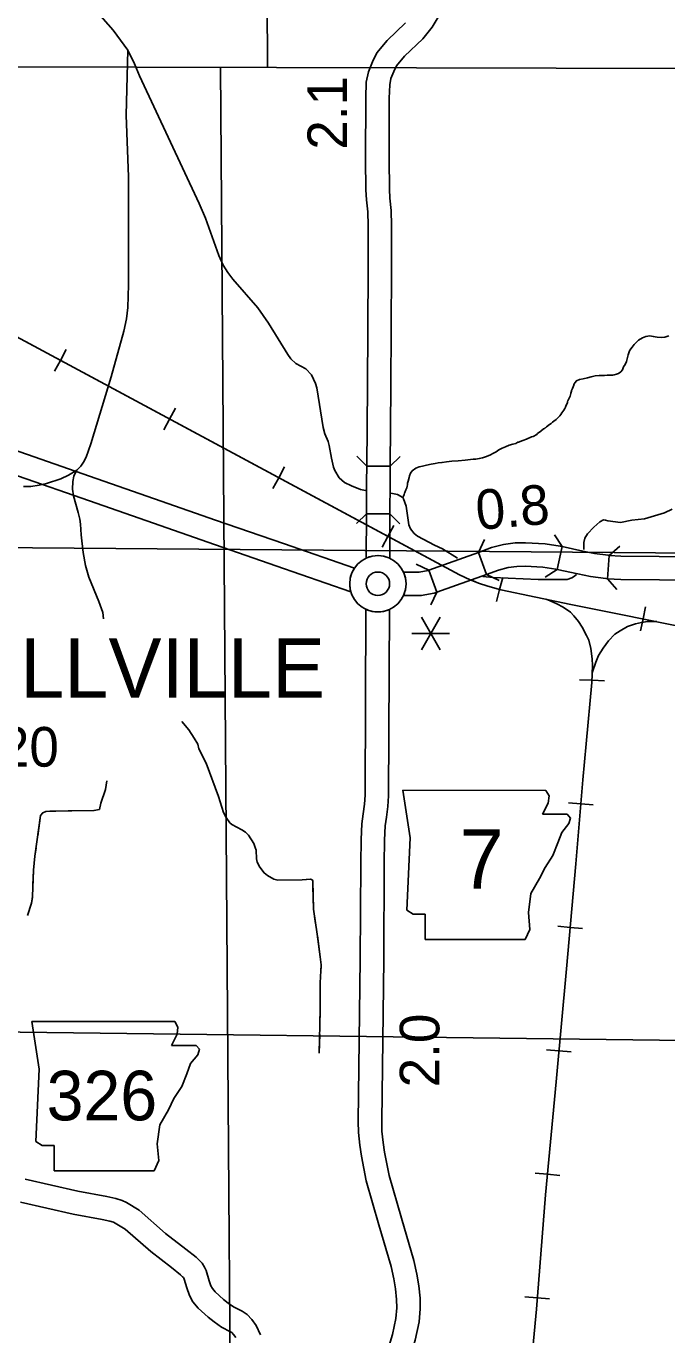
# Model space of a CAD drawing. Extents: x 1374139 to 1377472, y 1168351 to 1170484.
# Drawn here: x 1375232.8 to 1375369.3, y 1169137.4 to 1169416 of the extents above; entities that cross this region are included whole.
import ezdxf

# ---------------------------------------------------------------- set-up
doc = ezdxf.new("R2010")
doc.units = 0
doc.layers.add('Default', color=7, linetype='Continuous')

msp = doc.modelspace()

# ---------------------------------------------------------------- linework, layer by layer
at = {"layer": 'Default'}
for p, q in [((1375941.96, 1169405.45), (1375090, 1169407.73)), ((1375240.09, 1169344.85), (1375241.33, 1169347.18)), ((1375240.09, 1169344.85), (1375238.84, 1169342.53)), ((1375263.34, 1169332.36), (1375264.59, 1169334.69)), ((1375263.34, 1169332.36), (1375262.1, 1169330.04)), ((1375343.44, 1169330.52), (1375343.36, 1169330.48)), ((1375286.6, 1169319.87), (1375287.85, 1169322.2)), ((1375310.34, 1169322.3), (1375305.34, 1169322.34)), ((1375286.6, 1169319.87), (1375285.35, 1169317.55)), ((1375305.28, 1169312.21), (1375310.28, 1169312.18)), ((1375309.86, 1169307.38), (1375311.11, 1169309.71)), ((1375356.69, 1169310.67), (1375359.39, 1169310.31)), ((1375309.86, 1169307.38), (1375308.61, 1169305.06)), ((1375330.83, 1169299.29), (1375329.14, 1169303.99)), ((1375329.14, 1169303.99), (1375329.14, 1169303.99)), ((1375346.97, 1169305.23), (1375345.9, 1169300.34)), ((1375318.57, 1169300.2), (1375320.26, 1169295.49)), ((1375333.64, 1169296.1), (1375334.31, 1169298.65)), ((1375333.64, 1169296.1), (1375332.96, 1169293.54)), ((1375364.21, 1169289.84), (1375364.74, 1169292.42)), ((1375320.98, 1169290.19), (1375316.98, 1169283.26)), ((1375316.98, 1169290.19), (1375320.98, 1169283.26)), ((1375364.21, 1169289.84), (1375363.69, 1169287.25)), ((1375314.98, 1169286.73), (1375322.98, 1169286.73)), ((1375353.34, 1169276.74), (1375350.7, 1169276.85)), ((1375353.34, 1169276.74), (1375355.98, 1169276.64)), ((1375313.05, 1169253.33), (1375314.57, 1169243.18)), ((1375344.18, 1169252.15), (1375343.47, 1169253.32)), ((1375342.82, 1169248.26), (1375344.01, 1169250.62)), ((1375344.01, 1169250.62), (1375344.18, 1169252.15)), ((1375350.97, 1169250.45), (1375348.34, 1169250.68)), ((1375350.97, 1169250.45), (1375353.6, 1169250.23)), ((1375348.07, 1169248.26), (1375342.82, 1169248.26)), ((1375348.74, 1169247.41), (1375348.07, 1169248.26)), ((1375348.41, 1169246.23), (1375348.74, 1169247.41)), ((1375346.04, 1169242.17), (1375346.88, 1169244.36)), ((1375346.88, 1169244.36), (1375348.41, 1169246.23)), ((1375314.57, 1169243.18), (1375313.89, 1169227.79)), ((1375345.02, 1169239.46), (1375346.04, 1169242.17)), ((1375343.33, 1169236.92), (1375345.02, 1169239.46)), ((1375342.15, 1169234.55), (1375343.33, 1169236.92)), ((1375340.29, 1169231.34), (1375342.15, 1169234.55)), ((1375339.78, 1169227.28), (1375340.29, 1169231.34)), ((1375313.89, 1169227.79), (1375315.25, 1169226.94)), ((1375315.25, 1169226.94), (1375317.78, 1169226.94)), ((1375317.78, 1169226.94), (1375317.78, 1169221.53)), ((1375340.12, 1169223.72), (1375339.78, 1169227.28)), ((1375339.1, 1169221.53), (1375340.12, 1169223.72)), ((1375348.68, 1169224.15), (1375346.05, 1169224.38)), ((1375348.68, 1169224.15), (1375351.31, 1169223.92)), ((1375317.78, 1169221.53), (1375339.1, 1169221.53)), ((1375233.99, 1169204.11), (1375235.51, 1169193.96)), ((1375265.12, 1169202.92), (1375264.42, 1169204.09)), ((1375264.95, 1169201.4), (1375265.12, 1169202.92)), ((1375263.76, 1169199.03), (1375264.95, 1169201.4)), ((1375269.01, 1169199.03), (1375263.76, 1169199.03)), ((1375267.82, 1169195.14), (1375269.35, 1169197)), ((1375269.69, 1169198.19), (1375269.01, 1169199.03)), ((1375269.35, 1169197), (1375269.69, 1169198.19)), ((1375346.3, 1169197.86), (1375343.67, 1169198.1)), ((1375346.3, 1169197.86), (1375348.93, 1169197.62)), ((1375235.51, 1169193.96), (1375234.83, 1169178.56)), ((1375266.98, 1169192.94), (1375267.82, 1169195.14)), ((1375265.96, 1169190.24), (1375266.98, 1169192.94)), ((1375264.27, 1169187.7), (1375265.96, 1169190.24)), ((1375263.09, 1169185.33), (1375264.27, 1169187.7)), ((1375261.23, 1169182.11), (1375263.09, 1169185.33)), ((1375260.72, 1169178.05), (1375261.23, 1169182.11)), ((1375234.83, 1169178.56), (1375236.19, 1169177.72)), ((1375236.19, 1169177.72), (1375238.73, 1169177.72)), ((1375238.73, 1169177.72), (1375238.73, 1169172.3)), ((1375261.06, 1169174.5), (1375260.72, 1169178.05)), ((1375260.04, 1169172.3), (1375261.06, 1169174.5)), ((1375238.73, 1169172.3), (1375260.04, 1169172.3)), ((1375343.85, 1169171.57), (1375341.22, 1169171.82)), ((1375343.85, 1169171.57), (1375346.47, 1169171.33)), ((1375341.68, 1169145.26), (1375339.04, 1169145.47)), ((1375341.68, 1169145.26), (1375344.31, 1169145.05))]:
    msp.add_line(p, q, dxfattribs=at)
for points in [[(1375283.31, 1169579.43), (1375284.22, 1169407.21)], [(1375246.53, 1169420.57), (1375251.3, 1169415.14), (1375254.45, 1169410.89), (1375255.87, 1169407.97), (1375256.9, 1169405.47), (1375269.67, 1169378.27), (1375270.96, 1169375.13), (1375273.84, 1169367.17), (1375274.76, 1169365.13), (1375275.72, 1169363.56), (1375276.8, 1169362.12), (1375282.15, 1169356.04), (1375284.38, 1169352.78), (1375288.51, 1169346.13), (1375289.19, 1169345.22), (1375290.23, 1169344.16), (1375292.37, 1169343.04), (1375293.6, 1169341.76)], [(1375359.5, 1169290.79), (1375348.79, 1169292.9), (1375333.93, 1169296.02), (1375331.12, 1169296.76), (1375329.14, 1169297.45), (1375327.4, 1169298.17), (1375325.1, 1169299.2), (1375209.82, 1169361.1), (1375199.78, 1169366.23), (1375184.08, 1169373.76), (1375166.28, 1169381.99), (1375163.13, 1169383.65), (1375143.9, 1169395.21), (1375138.42, 1169398.64), (1375135.76, 1169400.59), (1375133.37, 1169402.41), (1375131.71, 1169403.89), (1375129.3, 1169406.1), (1375126.97, 1169408.87), (1375124.82, 1169411.94), (1375123.33, 1169413.94), (1375122.18, 1169415.76), (1375120.85, 1169417.96)], [(1375321.15, 1169301.32), (1375209.82, 1169361.1), (1375199.78, 1169366.23), (1375184.08, 1169373.76), (1375166.28, 1169381.99), (1375163.13, 1169383.65), (1375143.9, 1169395.21), (1375138.42, 1169398.64), (1375135.76, 1169400.59), (1375133.37, 1169402.41), (1375131.71, 1169403.89), (1375129.3, 1169406.1), (1375126.97, 1169408.87), (1375124.82, 1169411.94), (1375123.33, 1169413.94), (1375122.18, 1169415.76), (1375120.85, 1169417.96)], [(1375320.78, 1169418.25), (1375319.25, 1169415.79), (1375317.26, 1169413.3), (1375313.36, 1169409.59), (1375311.71, 1169407.56), (1375311.09, 1169406.35), (1375310.5, 1169404.89), (1375310.24, 1169403.51), (1375310.13, 1169400.65), (1375310.11, 1169387.61), (1375310.17, 1169381.34), (1375310.29, 1169379.42), (1375310.55, 1169376.75), (1375310.62, 1169373.59), (1375310.62, 1169364.18), (1375310.48, 1169339.25), (1375310.34, 1169322.3)], [(1375305.34, 1169322.34), (1375305.48, 1169339.28), (1375305.62, 1169364.2), (1375305.62, 1169373.54), (1375305.55, 1169376.45), (1375305.3, 1169379.04), (1375305.18, 1169381.17), (1375305.11, 1169387.59), (1375305.13, 1169400.75), (1375305.25, 1169404.08), (1375305.68, 1169406.32), (1375306.54, 1169408.44), (1375307.51, 1169410.31), (1375309.68, 1169412.99), (1375313.57, 1169416.69)], [(1375254.45, 1169410.89), (1375254.05, 1169397.03), (1375254.56, 1169383.94), (1375254.57, 1169360.91), (1375254.47, 1169356.14), (1375254.14, 1169353.69), (1375253.55, 1169351.05), (1375250.89, 1169341.33), (1375246.56, 1169327.12), (1375245.54, 1169324.27), (1375244.96, 1169323.18), (1375244.42, 1169322.34), (1375243.6, 1169321.49), (1375241.82, 1169320.45), (1375240.14, 1169319.65), (1375237.14, 1169318.63), (1375235.54, 1169318.26), (1375233.77, 1169318.02), (1375232.23, 1169318.01)], [(1375274.18, 1169407.24), (1375277.97, 1168899.53)], [(1375156.81, 1169351.32), (1375162.98, 1169349.27), (1375210.62, 1169332.61), (1375246.3, 1169320.21), (1375261.51, 1169314.91), (1375273.11, 1169310.87), (1375287.63, 1169305.88), (1375302.7, 1169300.62)], [(1375369.68, 1169350.06), (1375368.85, 1169349.8), (1375368.15, 1169349.74), (1375367.21, 1169349.8), (1375366.37, 1169349.95), (1375365.66, 1169350.06), (1375364.8, 1169349.97), (1375364.1, 1169349.66), (1375363.25, 1169349.18), (1375362.34, 1169348.25), (1375361.89, 1169347.68), (1375361.43, 1169347.02), (1375361.28, 1169346.66), (1375361.07, 1169346.01), (1375360.87, 1169345.46), (1375360.69, 1169344.6), (1375360.4, 1169343.97), (1375360.06, 1169343.48), (1375359.85, 1169342.85), (1375359.48, 1169342.42), (1375359.01, 1169342.09), (1375358.54, 1169341.94), (1375358.07, 1169341.8), (1375357.79, 1169341.74), (1375357.26, 1169341.74), (1375356.57, 1169341.71), (1375355.99, 1169341.67), (1375354.87, 1169341.62), (1375354.03, 1169341.54), (1375353.14, 1169341.36), (1375352.4, 1169341.14), (1375351.45, 1169340.92), (1375350.69, 1169340.8), (1375350.02, 1169340.5), (1375349.73, 1169340.17), (1375349.56, 1169339.89), (1375349.48, 1169339.62), (1375349.47, 1169339.56), (1375349.33, 1169339.24), (1375349.2, 1169338.89), (1375348.97, 1169338.45), (1375348.94, 1169338.27), (1375348.83, 1169337.86), (1375348.81, 1169337.8), (1375348.66, 1169337.22), (1375348.59, 1169337.07), (1375348.24, 1169336.42), (1375348.21, 1169336.3), (1375348.12, 1169336), (1375348.08, 1169335.9), (1375347.89, 1169335.39), (1375347.83, 1169335.29), (1375347.7, 1169334.93), (1375347.59, 1169334.72), (1375347.53, 1169334.6), (1375347.36, 1169334.28), (1375347.13, 1169333.99), (1375346.91, 1169333.68), (1375346.66, 1169333.32), (1375346.49, 1169333.07), (1375346.31, 1169332.89), (1375346.04, 1169332.66), (1375345.71, 1169332.3), (1375345.22, 1169331.94), (1375344.95, 1169331.71), (1375344.85, 1169331.65), (1375344.6, 1169331.44), (1375344.28, 1169331.21), (1375343.65, 1169330.71), (1375343.44, 1169330.52)], [(1375301.96, 1169295.58), (1375285.99, 1169301.15), (1375271.47, 1169306.14), (1375259.87, 1169310.19), (1375244.66, 1169315.49), (1375208.98, 1169327.88), (1375161.37, 1169344.54), (1375155.24, 1169346.57)], [(1375293.6, 1169341.76), (1375294.44, 1169339.97), (1375294.68, 1169338.98), (1375296.05, 1169330.55), (1375296.4, 1169329.19), (1375297.11, 1169327.6), (1375297.35, 1169326.76), (1375297.82, 1169324.03), (1375298.28, 1169322.15), (1375298.56, 1169321.44), (1375299.47, 1169319.87), (1375300.63, 1169318.87), (1375302.06, 1169318.12), (1375303.98, 1169317.4), (1375305.09, 1169317.17)], [(1375343.36, 1169330.48), (1375343.22, 1169330.38), (1375343.02, 1169330.28), (1375342.4, 1169329.8), (1375341.71, 1169329.26), (1375341.55, 1169329.1), (1375340.79, 1169328.62), (1375340.41, 1169328.55), (1375339.4, 1169328.06), (1375338.63, 1169327.8), (1375337.68, 1169327.47), (1375337.54, 1169327.41), (1375337.11, 1169327.18), (1375336.49, 1169327), (1375335.72, 1169326.84), (1375334.87, 1169326.46), (1375334.16, 1169326.14), (1375333.47, 1169325.84), (1375332.9, 1169325.37), (1375332.21, 1169325.01), (1375331.73, 1169324.74), (1375330.84, 1169324.38), (1375330.01, 1169324.1), (1375329.32, 1169323.94), (1375328.57, 1169323.85), (1375327.99, 1169323.79), (1375326.89, 1169323.65), (1375326.31, 1169323.6), (1375324.82, 1169323.44), (1375323.5, 1169323.37), (1375322.35, 1169323.24), (1375321.39, 1169323.15), (1375320.59, 1169323.01), (1375319.89, 1169322.87), (1375319.04, 1169322.73), (1375318.07, 1169322.53), (1375317.25, 1169322.35), (1375316.5, 1169322.17), (1375315.83, 1169321.89), (1375315.04, 1169321.33), (1375314.65, 1169320.86), (1375314.45, 1169320.29), (1375314.38, 1169319.89), (1375314.38, 1169319.91), (1375314.18, 1169319.16), (1375314.05, 1169318.71), (1375314, 1169318.34), (1375313.92, 1169318.07), (1375313.85, 1169317.69), (1375313.7, 1169317.27), (1375313.46, 1169316.7), (1375313.38, 1169316.56), (1375313.3, 1169316.33), (1375313.16, 1169315.95), (1375313.01, 1169315.64)], [(1375305.34, 1169322.34), (1375303.24, 1169324.48)], [(1375305.34, 1169322.34), (1375305.32, 1169319.03), (1375305.28, 1169312.21)], [(1375310.28, 1169312.18), (1375310.32, 1169318.99), (1375310.34, 1169322.3)], [(1375312.48, 1169324.41), (1375310.34, 1169322.3)], [(1375243.6, 1169321.49), (1375243.21, 1169320.86), (1375242.96, 1169320.21), (1375242.73, 1169319.1), (1375242.62, 1169317.42), (1375242.83, 1169316), (1375243.88, 1169312.49), (1375244.19, 1169311.08), (1375244.37, 1169309.98), (1375244.48, 1169307.75), (1375244.92, 1169303.94), (1375245.43, 1169301.18), (1375246.16, 1169298.73), (1375248.25, 1169293.54), (1375249.1, 1169291.19), (1375249.26, 1169289.85)], [(1375310.46, 1169316.59), (1375311.9, 1169316.28), (1375313.01, 1169315.64), (1375313.2, 1169315.36), (1375313.71, 1169313.83), (1375314.29, 1169309.81), (1375314.69, 1169308.96), (1375315.45, 1169308.01), (1375316.12, 1169307.46), (1375319.78, 1169305.49), (1375321.48, 1169304.75), (1375324.68, 1169302.74)], [(1375303.15, 1169310.1), (1375305.28, 1169312.21)], [(1375305.24, 1169302.77), (1375305.28, 1169312.21)], [(1375310.28, 1169312.18), (1375310.24, 1169302.75)], [(1375310.28, 1169312.18), (1375312.39, 1169310.05)], [(1375351.58, 1169304.56), (1375351.57, 1169306.1), (1375351.83, 1169307.02), (1375352.37, 1169307.92), (1375353.72, 1169309.37), (1375355.02, 1169310.48), (1375355.75, 1169310.89), (1375356.19, 1169310.86), (1375356.69, 1169310.67)], [(1375370.44, 1169313.18), (1375368.79, 1169312.37), (1375364.51, 1169311.13), (1375361.82, 1169310.83), (1375359.39, 1169310.31)], [(1375329.14, 1169303.99), (1375330.42, 1169306.71)], [(1375329.14, 1169303.99), (1375331.94, 1169304.99), (1375334.48, 1169305.67), (1375336.95, 1169306), (1375339.18, 1169306.04), (1375343.35, 1169305.82), (1375346.55, 1169305.32), (1375346.97, 1169305.23)], [(1375345.35, 1169307.75), (1375346.97, 1169305.23)], [(1375357.01, 1169303.35), (1375359.27, 1169305.32)], [(1375924.39, 1169299.41), (1375198.69, 1169305.24)], [(1375318.57, 1169300.2), (1375329.14, 1169303.99)], [(1375346.97, 1169305.23), (1375351.36, 1169304.27), (1375353.86, 1169303.76), (1375356.76, 1169303.37), (1375357.01, 1169303.35)], [(1375359.45, 1169298.18), (1375356.67, 1169298.36), (1375357.01, 1169303.35), (1375359.49, 1169303.18), (1375375.83, 1169303.05), (1375387.65, 1169303.73), (1375407.04, 1169303.86), (1375438.81, 1169303.7), (1375473.08, 1169303.31), (1375488.01, 1169303.36), (1375509.41, 1169303.21), (1375537.09, 1169303.05), (1375541.75, 1169302.78), (1375544.81, 1169302.36), (1375547.22, 1169301.84), (1375582.23, 1169293.42)], [(1375313.16, 1169299.8), (1375316.5, 1169299.8), (1375318.4, 1169300.14), (1375318.57, 1169300.2)], [(1375315.86, 1169301.48), (1375318.57, 1169300.2)], [(1375345.9, 1169300.34), (1375345.63, 1169300.4), (1375342.83, 1169300.84), (1375339.1, 1169301.04), (1375337.33, 1169301), (1375335.45, 1169300.76), (1375333.43, 1169300.22), (1375330.83, 1169299.29)], [(1375345.9, 1169300.34), (1375343.38, 1169298.72)], [(1375345.9, 1169300.34), (1375350.32, 1169299.38), (1375353.02, 1169298.82), (1375356.26, 1169298.39), (1375356.67, 1169298.36)], [(1375320.26, 1169295.49), (1375330.83, 1169299.29)], [(1375359.5, 1169290.79), (1375348.79, 1169292.9), (1375333.93, 1169296.02), (1375331.12, 1169296.76), (1375329.14, 1169297.45), (1375327.87, 1169297.98)], [(1375330.06, 1169298.84), (1375330.06, 1169298.84), (1375332.29, 1169298.62), (1375341.87, 1169298.24), (1375348.07, 1169298.22), (1375349.03, 1169298.56), (1375349.4, 1169298.79), (1375350, 1169299.26)], [(1375333.54, 1169298.01), (1375330.83, 1169299.29)], [(1375358.64, 1169296.1), (1375356.67, 1169298.36)], [(1375581.02, 1169288.57), (1375546.11, 1169296.97), (1375543.95, 1169297.43), (1375541.27, 1169297.8), (1375536.93, 1169298.05), (1375509.38, 1169298.21), (1375488, 1169298.36), (1375473.06, 1169298.31), (1375438.77, 1169298.7), (1375407.05, 1169298.86), (1375387.81, 1169298.73), (1375375.95, 1169298.05), (1375359.45, 1169298.18)], [(1375320.26, 1169295.49), (1375319.69, 1169295.29), (1375316.94, 1169294.8), (1375313.16, 1169294.8)], [(1375320.26, 1169295.49), (1375318.98, 1169292.78)], [(1375305.18, 1169291.86), (1375304.99, 1169252.28), (1375304.88, 1169250.38), (1375304.57, 1169248.3), (1375304.3, 1169246.2), (1375304.13, 1169242.84), (1375304.06, 1169237.77), (1375303.96, 1169217.33)], [(1375308.96, 1169217.31), (1375309.06, 1169237.72), (1375309.12, 1169242.68), (1375309.28, 1169245.75), (1375309.52, 1169247.61), (1375309.86, 1169249.87), (1375309.99, 1169252.12), (1375310.18, 1169291.84)], [(1375339.43, 1169121.14), (1375341.48, 1169142.85), (1375343.43, 1169167.17), (1375345.7, 1169191.29), (1375347.89, 1169215.33), (1375349.88, 1169237.64), (1375351.41, 1169255.56), (1375352.07, 1169263.25), (1375353.32, 1169276.28), (1375353.46, 1169279.87), (1375353.36, 1169281.3), (1375353.08, 1169283.51), (1375352.63, 1169285.29), (1375352.18, 1169286.27), (1375351.27, 1169288.04), (1375350.47, 1169289.3), (1375349.49, 1169290.45), (1375348.73, 1169291.25), (1375347.16, 1169292.33), (1375345.84, 1169293.06), (1375344.41, 1169293.69), (1375343.57, 1169294)], [(1375339.43, 1169121.14), (1375341.48, 1169142.85), (1375343.43, 1169167.17), (1375345.7, 1169191.29), (1375347.89, 1169215.33), (1375349.88, 1169237.64), (1375351.41, 1169255.56), (1375352.07, 1169263.25), (1375353.32, 1169276.28), (1375353.46, 1169279.87), (1375353.36, 1169281.3), (1375353.08, 1169283.51), (1375352.63, 1169285.29), (1375352.18, 1169286.27), (1375351.27, 1169288.04), (1375350.47, 1169289.3), (1375349.49, 1169290.45), (1375348.73, 1169291.25), (1375347.16, 1169292.33), (1375345.84, 1169293.06), (1375344.41, 1169293.69), (1375343.57, 1169294)], [(1375353.4, 1169278.32), (1375354.13, 1169280.59), (1375354.72, 1169282.05), (1375355.69, 1169283.62), (1375356.84, 1169285.12), (1375358.2, 1169286.55), (1375359.35, 1169287.31), (1375360.91, 1169288.18), (1375362.62, 1169288.74), (1375363.91, 1169289.05), (1375365.13, 1169289.26), (1375365.82, 1169289.3), (1375367.15, 1169289.24)], [(1375414.8, 1169279.56), (1375359.5, 1169290.79)], [(1375414.8, 1169279.56), (1375359.5, 1169290.79)], [(1375265.96, 1169267.98), (1375267.43, 1169266.21), (1375268.55, 1169264.41), (1375269.34, 1169263.14), (1375269.56, 1169262.13), (1375271.11, 1169259.07), (1375273.74, 1169252.01), (1375274.83, 1169248.62), (1375275.39, 1169247.51), (1375276.17, 1169246.41), (1375276.62, 1169246.04), (1375278.74, 1169244.92), (1375279.52, 1169244.39), (1375280.13, 1169243.8), (1375281.26, 1169242.02), (1375281.6, 1169241.15), (1375281.75, 1169240.59), (1375281.87, 1169238.75), (1375282, 1169238.05), (1375282.53, 1169236.94), (1375283.45, 1169235.75), (1375284.16, 1169235.19), (1375285.54, 1169234.43)], [(1375249.97, 1169255.31), (1375249.71, 1169253.53), (1375248.69, 1169250.62), (1375248.42, 1169249.25)], [(1375313.05, 1169253.33), (1375343.47, 1169253.32)], [(1375233.08, 1169226.69), (1375233.93, 1169229.28), (1375234.12, 1169230.74), (1375234.36, 1169236.32), (1375234.62, 1169239.33), (1375235.86, 1169247.95), (1375236.32, 1169248.56), (1375236.93, 1169248.82), (1375237.85, 1169248.91), (1375247.2, 1169249), (1375248.42, 1169249.25)], [(1375235.24, 1169243.65), (1375235.86, 1169247.95), (1375236.32, 1169248.56), (1375236.93, 1169248.82), (1375237.85, 1169248.91), (1375239.07, 1169248.92)], [(1375241.71, 1169248.94), (1375247.2, 1169249), (1375248.42, 1169249.25)], [(1375234.22, 1169233.14), (1375234.36, 1169236.32), (1375234.62, 1169239.33), (1375234.87, 1169241.03)], [(1375295.22, 1169197.36), (1375295.43, 1169206.42), (1375295.43, 1169212.33), (1375295.63, 1169216.2), (1375295.45, 1169217.88), (1375294.77, 1169222.73), (1375293.98, 1169228.02), (1375293.85, 1169234.03), (1375293.72, 1169234.24), (1375293.59, 1169234.34), (1375293.29, 1169234.42), (1375291.61, 1169234.29), (1375286.42, 1169234.16), (1375285.54, 1169234.43)], [(1375292.53, 1169234.36), (1375291.61, 1169234.29), (1375286.42, 1169234.16), (1375285.54, 1169234.43)], [(1375294.43, 1169224.98), (1375293.98, 1169228.02), (1375293.87, 1169232.87)], [(1375233.08, 1169226.69), (1375233.93, 1169229.28), (1375234.09, 1169230.51)], [(1375295.54, 1169214.51), (1375295.63, 1169216.2), (1375295.45, 1169217.88), (1375294.82, 1169222.37)], [(1375303.96, 1169217.35), (1375303.54, 1169182.85), (1375303.59, 1169180.48), (1375303.86, 1169177.75), (1375304.21, 1169175.41), (1375305.24, 1169170.15), (1375307.93, 1169160.85), (1375310.54, 1169151.94), (1375311.12, 1169149.35), (1375311.5, 1169147.19), (1375311.7, 1169144.93), (1375311.72, 1169143.13), (1375311.53, 1169140.89), (1375310.82, 1169137.5), (1375310.09, 1169135.1), (1375308.99, 1169132.51), (1375301.47, 1169117.13), (1375291.53, 1169096.56)], [(1375296.03, 1169094.38), (1375305.97, 1169114.94), (1375313.53, 1169130.43), (1375314.8, 1169133.39), (1375315.66, 1169136.26), (1375316.49, 1169140.16), (1375316.72, 1169142.95), (1375316.69, 1169145.17), (1375316.47, 1169147.85), (1375316.02, 1169150.33), (1375315.39, 1169153.19), (1375312.73, 1169162.25), (1375310.11, 1169171.32), (1375309.14, 1169176.26), (1375308.83, 1169178.37), (1375308.59, 1169180.78), (1375308.54, 1169182.88), (1375308.96, 1169217.29)], [(1375295.37, 1169203.95), (1375295.43, 1169206.42), (1375295.43, 1169211.87)], [(1375197.41, 1169202.24), (1375923.92, 1169193.18)], [(1375233.99, 1169204.11), (1375264.42, 1169204.09)], [(1375295.22, 1169197.36), (1375295.31, 1169201.31)], [(1375232.56, 1169170.55), (1375243.77, 1169168.01), (1375249.99, 1169166.84), (1375251.87, 1169166.43), (1375253.2, 1169166.03), (1375254.13, 1169165.58), (1375256.83, 1169163.91), (1375262.49, 1169158.99), (1375266.79, 1169155.67), (1375268.97, 1169153.96), (1375269.63, 1169153.32), (1375270.29, 1169152.64), (1375270.77, 1169151.81), (1375271.15, 1169151.06), (1375271.76, 1169148.9), (1375272.15, 1169147.8), (1375272.45, 1169147.23), (1375273.04, 1169146.55), (1375274.8, 1169144.95), (1375275.82, 1169144.14), (1375276.96, 1169143.34), (1375278.81, 1169142.42), (1375279.84, 1169141.75), (1375280.85, 1169140.65), (1375281.76, 1169139.38), (1375282.73, 1169137.41)], [(1375277.45, 1169136.8), (1375276.96, 1169137.49), (1375276.58, 1169137.9), (1375276.32, 1169138.07), (1375274.39, 1169139.03), (1375272.82, 1169140.14), (1375271.56, 1169141.14), (1375269.45, 1169143.05), (1375268.28, 1169144.4), (1375267.56, 1169145.79), (1375266.99, 1169147.38), (1375266.47, 1169149.24), (1375266.37, 1169149.43), (1375266.27, 1169149.6), (1375266.1, 1169149.78), (1375265.68, 1169150.18), (1375263.72, 1169151.72), (1375259.32, 1169155.12), (1375253.86, 1169159.87), (1375251.74, 1169161.19), (1375251.38, 1169161.35), (1375250.61, 1169161.59), (1375248.99, 1169161.94), (1375242.76, 1169163.11), (1375231.55, 1169165.65)]]:
    msp.add_lwpolyline(points, dxfattribs=at)
for radius, start, end in [(6, 90, 270), (6, 65.0947, 114.3435), (6, 270, 90), (6, 146.5086, 196.716), (2.5, 90, 270), (2.5, 270, 90), (6, 335.3756, 24.6242), (6, 245.0947, 294.3435)]:
    msp.add_arc((1375307.71, 1169297.3), radius, start, end, dxfattribs=at)

# ---------------------------------------------------------------- texts
for s, rotation, p in [('2.1', 90, (1375301.16, 1169389.71)), ('0.8', 5.0578, (1375328.93, 1169308.74)), ('2.0', 90, (1375320.82, 1169190.08))]:
    msp.add_text(s, height=8.448, rotation=rotation, dxfattribs=at).set_placement(p)
for s, height, p in [('RUSSELLVILLE', 12.672, (1375173.08, 1169273.02)), ('Pop. 27,920', 8.448, (1375178.81, 1169258.36)), ('7', 12.67, (1375325.1, 1169232.37)), ('326', 10.56, (1375237.13, 1169183.06))]:
    msp.add_text(s, height=height, dxfattribs=at).set_placement(p)

doc.saveas('drawing.dxf')
